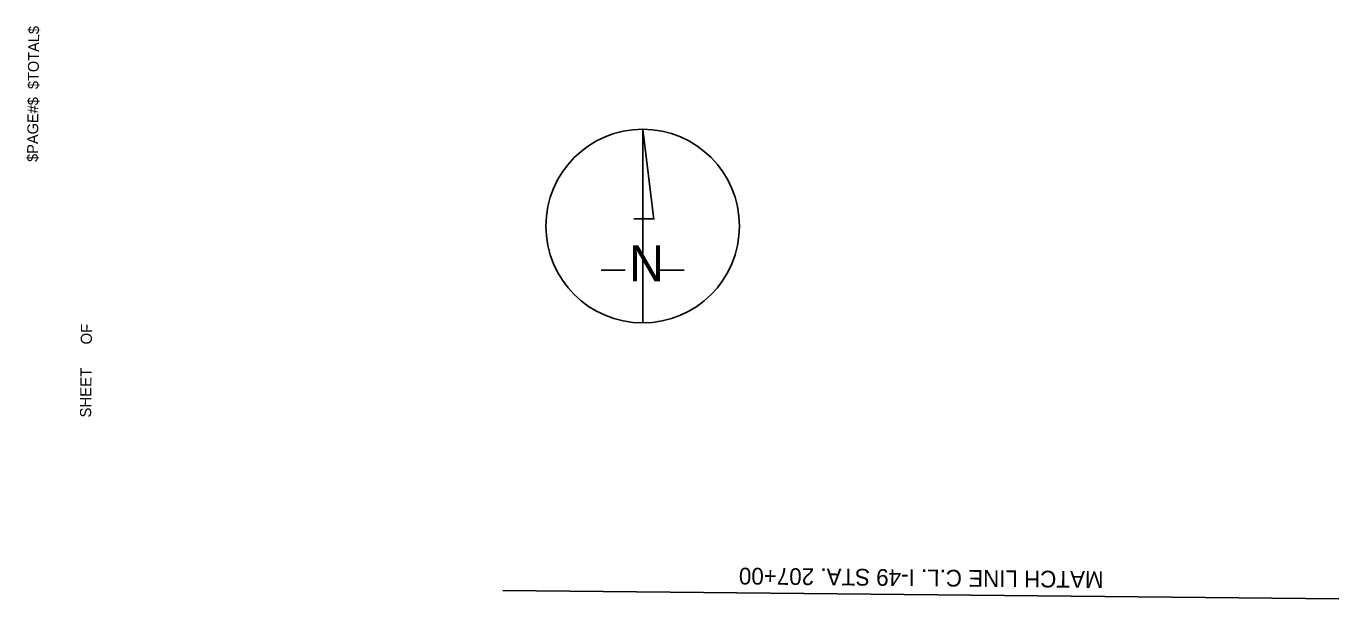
# Model space of a CAD drawing. Extents: x 631355 to 632768, y 375104 to 378144.
import ezdxf

# ---------------------------------------------------------------- set-up
doc = ezdxf.new("R2010")
doc.units = 0
for name, color, linetype in [('R_Border', 7, 'Continuous'), ('R_Border Notes', 7, 'Continuous'), ('R_Border_N Arrow', 7, 'Continuous'), ('R_No Plot', 7, 'Continuous')]:
    doc.layers.add(name, color=color, linetype=linetype)

msp = doc.modelspace()

# ---------------------------------------------------------------- linework, layer by layer
at = {"layer": 'R_Border'}
msp.add_line((631867.9, 377536.9), (632767.8, 377528), dxfattribs=at)
at = {"layer": 'R_Border_N Arrow'}
for p, q in [((632018.4, 378033), (632030.5, 377936.1)), ((632018.4, 377897.4), (632018.4, 378033)), ((632009, 377936.8), (632030.6, 377936.8)), ((631973.8, 377881.5), (631999.5, 377881.5)), ((632035.5, 377881.5), (632063, 377881.5)), ((632018.4, 377824.7), (632018.4, 377864.6))]:
    msp.add_line(p, q, dxfattribs=at)
at = {"layer": 'R_No Plot'}
msp.add_line((632018.4, 378033), (632018.4, 377824.7), dxfattribs=at)
msp.add_circle((632018.4, 377928.9), 104.2, dxfattribs=at)

# ---------------------------------------------------------------- texts
at = {"layer": 'R_Border'}
for s, p in [('$TOTAL$', (631368, 378076.2)), ('$PAGE#$', (631367.2, 377997.9))]:
    msp.add_text(s, height=11.72, rotation=89.4304, dxfattribs=at).set_placement(p)
at = {"layer": 'R_Border Notes'}
msp.add_text('MATCH LINE C.L. I-49 STA. 207+00', height=18, rotation=179.4304, dxfattribs=at).set_placement((632514.7, 377557.5))
at = {"layer": 'R_Border_N Arrow'}
msp.add_text('N', height=38.8, rotation=360, dxfattribs=at).set_placement((632003.7, 377869.5))
at = {"layer": 'R_No Plot'}
for s, p in [('OF', (631425.3, 377801.5)), ('SHEET', (631424.5, 377722.9))]:
    msp.add_text(s, height=12, rotation=89.4304, dxfattribs=at).set_placement(p)

doc.saveas('drawing.dxf')
